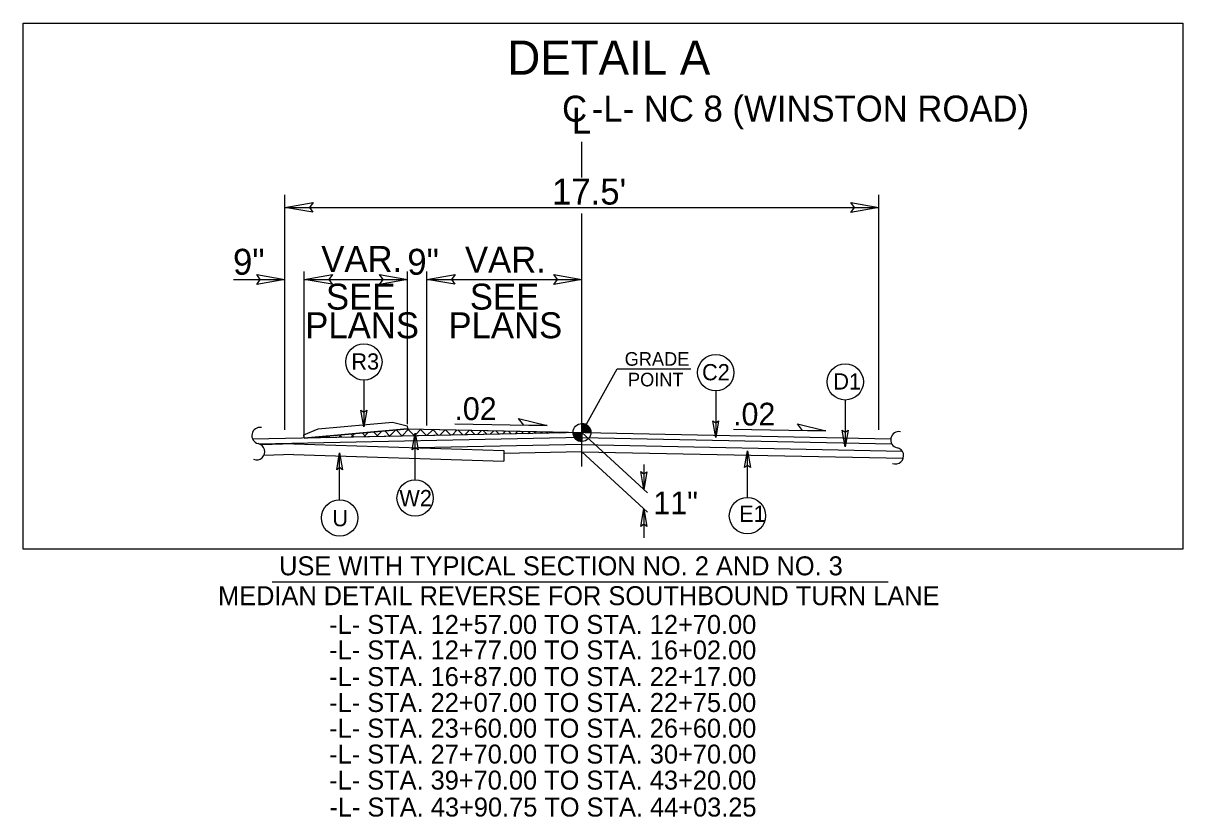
# Model space of a CAD drawing. Extents: x 957297 to 961629, y 830661 to 840840.
# Drawn here: x 960706.7 to 961104.7, y 838935.9 to 839208.2 of the extents above; entities that cross this region are included whole.
import ezdxf

# ---------------------------------------------------------------- set-up
doc = ezdxf.new("R2010")
doc.units = 0
for name, color, linetype in [('Old_Level_1', 7, 'Continuous'), ('Old_Level_11', 7, 'Continuous'), ('Old_Level_3', 7, 'Continuous'), ('Prop Dimension Text', 7, 'Continuous'), ('Typical ID Circle CELL', 7, 'Continuous'), ('Typical Terminator CELL', 7, 'Continuous'), ('Typical Text Grade Point CELL', 7, 'Continuous'), ('Typical Text ID Circle CELL', 7, 'Continuous')]:
    doc.layers.add(name, color=color, linetype=linetype)

msp = doc.modelspace()

# ---------------------------------------------------------------- linework, layer by layer
at = {"layer": 'Old_Level_1'}
for p, q in [((960898.52, 839155.33), (960898.52, 839167.52)), ((960796.56, 839068.71), (960796.56, 839149.38)), ((961000.47, 839068.71), (961000.47, 839149.38)), ((960796.56, 839145), (961000.47, 839145)), ((960898.52, 839056.06), (960898.52, 839142.96)), ((960778.93, 839120.3), (960796.56, 839120.3)), ((960803.21, 839065.85), (960803.21, 839123.05)), ((960803.21, 839120.3), (960838.67, 839120.3)), ((960838.67, 839070.68), (960838.67, 839123.05)), ((960845.32, 839070.15), (960845.32, 839123.05)), ((960845.32, 839120.3), (960898.52, 839120.3)), ((960898.52, 839067.78), (960910.57, 839089.56)), ((960838.61, 839068.99), (961004.51, 839065.63)), ((960854.93, 839070.79), (960886.53, 839070.15)), ((960898.52, 839067.78), (960898.52, 839070.84)), ((960950.58, 839068.93), (960982.18, 839068.3)), ((960898.52, 839067.78), (960785.49, 839065.49)), ((960898.52, 839066.05), (960787.89, 839063.81)), ((960895.45, 839067.78), (960898.52, 839067.78)), ((960901.58, 839067.78), (960898.52, 839067.78)), ((960898.52, 839064.73), (960898.52, 839067.78)), ((960898.52, 839067.78), (960898.52, 839064.73)), ((960898.52, 839067.78), (960921.02, 839047.06)), ((960898.52, 839066.05), (961004.85, 839063.9)), ((960930.2, 839065.45), (960930.24, 839065.4)), ((960898.52, 839063.62), (960842.44, 839062.49)), ((960871.72, 839061.57), (960871.72, 839057.89)), ((960898.52, 839061.13), (960871.72, 839060.59)), ((960898.52, 839063.62), (961008.41, 839061.4)), ((960898.52, 839061.13), (961008.79, 839058.9)), ((960898.52, 839061.13), (960921.02, 839040.41)), ((960919.76, 839056.73), (960919.76, 839048.22)), ((960919.75, 839041.59), (960919.75, 839031.63)), ((960792.18, 839016.56), (961003.59, 839016.56))]:
    msp.add_line(p, q, dxfattribs=at)
msp.add_lwpolyline([(960706.74, 839208.24), (961104.74, 839208.24), (961104.74, 839027.68), (960706.74, 839027.68)], close=True, dxfattribs=at)
for points in [[(960898.55, 839070.84), (960898.55, 839070.84), (960898.55, 839067.78)], [(960898.61, 839070.84), (960898.61, 839067.78)], [(960898.67, 839070.84), (960898.67, 839067.78)], [(960898.74, 839070.83), (960898.74, 839067.78)], [(960898.8, 839070.83), (960898.8, 839067.78)], [(960898.86, 839070.83), (960898.86, 839067.78)], [(960898.92, 839070.81), (960898.92, 839067.78)], [(960898.98, 839070.81), (960898.98, 839067.78)], [(960899.03, 839070.79), (960899.03, 839067.78)], [(960899.09, 839070.79), (960899.09, 839067.78)], [(960899.16, 839070.78), (960899.16, 839067.78)], [(960899.22, 839070.76), (960899.22, 839067.78)], [(960899.28, 839070.74), (960899.28, 839067.78)], [(960899.34, 839070.72), (960899.34, 839067.78)], [(960899.41, 839070.71), (960899.41, 839067.78)], [(960899.46, 839070.68), (960899.46, 839067.78)], [(960899.53, 839070.67), (960899.53, 839067.78)], [(960899.59, 839070.65), (960899.59, 839067.78)], [(960899.65, 839070.63), (960899.65, 839067.78)], [(960899.72, 839070.6), (960899.72, 839067.78)], [(960899.78, 839070.58), (960899.78, 839067.78)], [(960899.84, 839070.54), (960899.84, 839067.78)], [(960899.89, 839070.52), (960899.89, 839067.78)], [(960899.95, 839070.49), (960899.95, 839067.78)], [(960900.01, 839070.46), (960900.01, 839067.78)], [(960900.08, 839070.42), (960900.08, 839067.78)], [(960900.14, 839070.38), (960900.14, 839067.78)], [(960900.2, 839070.33), (960900.2, 839067.78)], [(960900.26, 839070.29), (960900.26, 839067.78)], [(960900.32, 839070.26), (960900.32, 839067.78)], [(960900.38, 839070.21), (960900.38, 839067.78)], [(960900.44, 839070.16), (960900.44, 839067.78)], [(960900.51, 839070.11), (960900.51, 839067.78)], [(960900.57, 839070.05), (960900.57, 839067.78)], [(960900.63, 839069.99), (960900.63, 839067.78)], [(960900.7, 839069.93), (960900.7, 839067.78)], [(960900.75, 839069.87), (960900.75, 839067.78)], [(960900.81, 839069.81), (960900.81, 839067.78)], [(960900.87, 839069.74), (960900.87, 839067.78)], [(960900.93, 839069.65), (960900.93, 839067.78)], [(960901, 839069.58), (960901, 839067.78)], [(960901.06, 839069.49), (960901.06, 839067.78)], [(960901.12, 839069.4), (960901.12, 839067.78)], [(960901.17, 839069.29), (960901.17, 839067.78)], [(960901.23, 839069.19), (960901.23, 839067.78)], [(960901.3, 839069.04), (960901.3, 839067.78)], [(960901.36, 839068.9), (960901.36, 839067.78)], [(960901.42, 839068.74), (960901.42, 839067.78)], [(960901.49, 839068.53), (960901.49, 839067.78)], [(960901.55, 839068.22), (960901.55, 839067.78)], [(960895.48, 839067.78), (960895.48, 839067.46)], [(960895.54, 839067.78), (960895.54, 839067.09)], [(960895.6, 839067.78), (960895.6, 839066.87)], [(960895.66, 839067.78), (960895.66, 839066.69)], [(960895.73, 839067.78), (960895.73, 839066.55)], [(960895.79, 839067.78), (960895.79, 839066.42)], [(960895.84, 839067.78), (960895.84, 839066.3)], [(960895.9, 839067.78), (960895.9, 839066.19)], [(960895.97, 839067.78), (960895.97, 839066.1)], [(960896.03, 839067.78), (960896.03, 839066.01)], [(960896.09, 839067.78), (960896.09, 839065.92)], [(960896.15, 839067.78), (960896.15, 839065.85)], [(960896.21, 839067.78), (960896.21, 839065.79)], [(960896.27, 839067.78), (960896.27, 839065.71)], [(960896.33, 839067.78), (960896.33, 839065.64)], [(960896.4, 839067.78), (960896.4, 839065.59)], [(960896.46, 839067.78), (960896.46, 839065.54)], [(960896.52, 839067.78), (960896.52, 839065.47)], [(960896.58, 839067.78), (960896.58, 839065.43)], [(960896.65, 839067.78), (960896.65, 839065.37)], [(960896.7, 839067.78), (960896.7, 839065.33)], [(960896.76, 839067.78), (960896.76, 839065.28)], [(960896.82, 839067.78), (960896.82, 839065.25)], [(960896.88, 839067.78), (960896.88, 839065.19)], [(960896.95, 839067.78), (960896.95, 839065.16)], [(960897.01, 839067.78), (960897.01, 839065.12)], [(960897.07, 839067.78), (960897.07, 839065.09)], [(960897.13, 839067.78), (960897.13, 839065.07)], [(960897.19, 839067.78), (960897.19, 839065.03)], [(960897.25, 839067.78), (960897.25, 839065)], [(960897.32, 839067.78), (960897.32, 839064.98)], [(960897.38, 839067.78), (960897.38, 839064.94)], [(960897.44, 839067.78), (960897.44, 839064.93)], [(960897.5, 839067.78), (960897.5, 839064.9)], [(960897.55, 839067.78), (960897.55, 839064.88)], [(960897.62, 839067.78), (960897.62, 839064.87)], [(960897.68, 839067.78), (960897.68, 839064.84)], [(960897.74, 839067.78), (960897.74, 839064.83)], [(960897.8, 839067.78), (960897.8, 839064.82)], [(960897.86, 839067.78), (960897.86, 839064.8)], [(960897.93, 839067.78), (960897.93, 839064.78)], [(960897.98, 839067.78), (960897.98, 839064.78)], [(960898.04, 839067.78), (960898.04, 839064.77)], [(960898.11, 839067.78), (960898.11, 839064.75)], [(960898.17, 839067.78), (960898.17, 839064.75)], [(960898.23, 839067.78), (960898.23, 839064.75)], [(960898.3, 839067.78), (960898.3, 839064.73)], [(960898.36, 839067.78), (960898.36, 839064.73)], [(960898.41, 839067.78), (960898.41, 839064.73)], [(960898.47, 839067.78), (960898.47, 839064.73), (960898.47, 839064.73)], [(960799.59, 839063.84), (960788.38, 839063.56)], [(960799.59, 839063.84), (960871.72, 839061.57)], [(960799.48, 839060.16), (960789.31, 839059.84)], [(960799.48, 839060.16), (960871.72, 839057.89)]]:
    msp.add_lwpolyline(points, dxfattribs=at)
msp.add_circle((960898.52, 839067.78), 3.06, dxfattribs=at)
for centre, radius, start, end in [((960788.03, 839066.7), 2.81, 79.4545, 256.8065), ((960898.52, 839067.78), 3.06, 359.9905, 89.9905), ((960898.52, 839067.78), 3.06, 179.9905, 269.9905), ((961007.3, 839065.27), 2.81, 79.4545, 256.8065), ((960786.85, 839061.2), 2.81, 248.3355, 78.8593), ((961006.12, 839059.77), 2.81, 248.3355, 78.8593)]:
    msp.add_arc(centre, radius, start, end, dxfattribs=at)
at = {"layer": 'Old_Level_11'}
for p, q in [((960878.52, 839070.31), (960876.79, 839072.57)), ((960876.79, 839072.57), (960886.53, 839070.15)), ((960886.53, 839070.15), (960878.52, 839070.31)), ((960974.18, 839068.46), (960972.45, 839070.71)), ((960972.45, 839070.71), (960982.18, 839068.3)), ((960982.18, 839068.3), (960974.18, 839068.46))]:
    msp.add_line(p, q, dxfattribs=at)
for points in [[(960806.18, 839143.35), (960796.56, 839145), (960806.23, 839146.71), (960805, 839145)], [(960990.85, 839146.66), (961000.47, 839145), (960990.8, 839143.29), (960992.03, 839145)], [(960786.95, 839121.95), (960796.56, 839120.3), (960786.89, 839118.59), (960788.12, 839120.3)], [(960812.83, 839118.64), (960803.21, 839120.3), (960812.88, 839122.01), (960811.65, 839120.3)], [(960829.06, 839121.95), (960838.67, 839120.3), (960829.01, 839118.59), (960830.24, 839120.3)], [(960854.94, 839118.64), (960845.32, 839120.3), (960854.99, 839122.01), (960853.76, 839120.3)], [(960888.9, 839121.95), (960898.52, 839120.3), (960888.85, 839118.59), (960890.08, 839120.3)]]:
    msp.add_lwpolyline(points, close=True, dxfattribs=at)
at = {"layer": 'Old_Level_3'}
for p, q in [((960803.11, 839066.95), (960807.96, 839069.06)), ((960838.6, 839068.99), (960803.21, 839065.85)), ((960807.96, 839069.06), (960833.44, 839071.32)), ((960827.99, 839066.35), (960829.85, 839068.21)), ((960830.85, 839068.3), (960832.7, 839066.44)), ((960832.32, 839066.44), (960834.51, 839068.62)), ((960833.44, 839071.32), (960838.58, 839070.1)), ((960834.74, 839068.64), (960836.86, 839066.53)), ((960836.65, 839066.52), (960839.11, 839068.98)), ((960838.58, 839070.1), (960838.6, 839068.99)), ((960838.64, 839068.99), (960841.02, 839066.61)), ((960841.38, 839067), (960843.26, 839068.89)), ((960842.97, 839068.9), (960845.18, 839066.7)), ((960845.31, 839066.7), (960847.42, 839068.81)), ((960847.3, 839068.81), (960849.33, 839066.78)), ((960849.65, 839066.79), (960851.58, 839068.72)), ((960851.63, 839068.72), (960853.49, 839066.87)), ((960853.98, 839066.87), (960855.74, 839068.64)), ((960855.96, 839068.64), (960857.65, 839066.95)), ((960858.31, 839066.96), (960859.9, 839068.56)), ((960860.29, 839068.55), (960861.81, 839067.03)), ((960862.64, 839067.05), (960864.06, 839068.47)), ((960864.63, 839068.46), (960865.97, 839067.12)), ((960866.97, 839067.14), (960868.22, 839068.39)), ((960868.96, 839068.37), (960870.13, 839067.2)), ((960871.3, 839067.23), (960872.37, 839068.3)), ((960873.29, 839068.28), (960874.28, 839067.29)), ((960875.63, 839067.31), (960876.53, 839068.22)), ((960803.21, 839065.85), (960803.11, 839066.95)), ((960803.57, 839065.88), (960803.59, 839065.86)), ((960806.34, 839065.91), (960806.58, 839066.15)), ((960807.46, 839066.23), (960807.75, 839065.94)), ((960810.67, 839066), (960811.23, 839066.56)), ((960811.36, 839066.57), (960811.91, 839066.02)), ((960815, 839066.09), (960815.89, 839066.97)), ((960815.26, 839066.92), (960816.07, 839066.11)), ((960819.15, 839067.26), (960820.22, 839066.19)), ((960819.33, 839066.17), (960820.54, 839067.38)), ((960823.05, 839067.61), (960824.38, 839066.28)), ((960823.66, 839066.26), (960825.2, 839067.8)), ((960826.95, 839067.95), (960828.54, 839066.36)), ((960840.98, 839066.61), (960841.13, 839066.76)), ((960877.62, 839068.2), (960878.44, 839067.37)), ((960879.96, 839067.4), (960880.69, 839068.14)), ((960881.95, 839068.11), (960882.6, 839067.45)), ((960884.29, 839067.49), (960884.85, 839068.05)), ((960886.28, 839068.02), (960886.76, 839067.54)), ((960888.62, 839067.58), (960889.01, 839067.97)), ((960890.61, 839067.93), (960890.92, 839067.62)), ((960892.95, 839067.66), (960893.17, 839067.88)), ((960894.94, 839067.85), (960895.08, 839067.71))]:
    msp.add_line(p, q, dxfattribs=at)
msp.add_lwpolyline([(960803.21, 839065.85), (960838.6, 839068.99), (960898.52, 839067.78)], close=True, dxfattribs=at)
at = {"layer": 'Typical ID Circle CELL'}
for p, q in [((960823.67, 839085.75), (960823.67, 839069.66)), ((960944.45, 839082.09), (960944.45, 839066)), ((960988.89, 839078.91), (960988.89, 839062.82)), ((960841.27, 839051.5), (960841.27, 839067.58)), ((960815.36, 839044.67), (960815.36, 839060.75)), ((960955.32, 839045.43), (960955.32, 839061.52))]:
    msp.add_line(p, q, dxfattribs=at)
for centre in [(960823.67, 839091.98), (960944.45, 839088.31), (960988.89, 839085.14), (960841.27, 839045.27), (960815.36, 839038.44), (960955.32, 839039.21)]:
    msp.add_circle(centre, 6.23, dxfattribs=at)
at = {"layer": 'Typical Terminator CELL'}
for points in [[(960824.66, 839075.43), (960823.67, 839069.66), (960822.64, 839075.46), (960823.67, 839074.72)], [(960945.44, 839071.77), (960944.45, 839066), (960943.42, 839071.8), (960944.45, 839071.06)], [(960989.88, 839068.59), (960988.89, 839062.82), (960987.87, 839068.62), (960988.89, 839067.88)], [(960840.28, 839061.82), (960841.27, 839067.58), (960842.3, 839061.79), (960841.27, 839062.52)], [(960814.37, 839054.99), (960815.36, 839060.75), (960816.39, 839054.96), (960815.36, 839055.7)], [(960954.33, 839055.76), (960955.32, 839061.52), (960956.35, 839055.73), (960955.32, 839056.46)], [(960920.81, 839054.29), (960919.76, 839048.22), (960918.68, 839054.33), (960919.76, 839053.55)], [(960918.7, 839035.52), (960919.75, 839041.59), (960920.82, 839035.49), (960919.75, 839036.27)]]:
    msp.add_lwpolyline(points, close=True, dxfattribs=at)
at = {"layer": 'Typical Text Grade Point CELL'}
msp.add_line((960910.57, 839089.56), (960935.9, 839089.56), dxfattribs=at)

# ---------------------------------------------------------------- texts
at = {"layer": 'Old_Level_1'}
for s, height, p in [('DETAIL A', 11.716, (960872.9, 839190.57)), ('USE WITH TYPICAL SECTION NO. 2 AND NO. 3', 6.5088, (960794.59, 839018.75)), ('MEDIAN DETAIL REVERSE FOR SOUTHBOUND TURN LANE', 6.5088, (960773.63, 839008.5)), ('-L- STA. 12+57.00 TO STA. 12+70.00', 6.5088, (960811.76, 838998.64)), ('-L- STA. 12+77.00 TO STA. 16+02.00', 6.5088, (960811.76, 838989.89)), ('-L- STA. 16+87.00 TO STA. 22+17.00', 6.5088, (960811.76, 838980.73)), ('-L- STA. 22+07.00 TO STA. 22+75.00', 6.5088, (960811.76, 838971.85)), ('-L- STA. 23+60.00 TO STA. 26+60.00', 6.5088, (960811.76, 838963.03)), ('-L- STA. 27+70.00 TO STA. 30+70.00', 6.5088, (960811.76, 838954.14)), ('-L- STA. 39+70.00 TO STA. 43+20.00', 6.5088, (960811.76, 838945.21)), ('-L- STA. 43+90.75 TO STA. 44+03.25', 6.5088, (960811.84, 838935.96))]:
    msp.add_text(s, height=height, dxfattribs=at).set_placement(p)
at = {"layer": 'Old_Level_11'}
for s, p in [('GRADE', (960913.17, 839090.68)), ('POINT', (960914.31, 839083.6))]:
    msp.add_text(s, height=4.671, dxfattribs=at).set_placement(p)
at = {"layer": 'Old_Level_3'}
for s, p in [("17.5'", (960888.27, 839145.99)), ('9"', (960778.76, 839121.91)), ('VAR.', (960809.05, 839122.87)), ('9"', (960838.59, 839121.91)), ('VAR.', (960858.37, 839122.63)), ('SEE', (960810.66, 839109.95)), ('SEE', (960860.04, 839109.95)), ('PLANS', (960803.55, 839100.11)), ('PLANS', (960852.71, 839100.11))]:
    msp.add_text(s, height=8.9, rotation=0, dxfattribs=at).set_placement(p)
at = {"layer": 'Prop Dimension Text'}
for s, height, rotation, p in [('-L- NC 8 (WINSTON ROAD)', 8.9003, 0, (960901.9, 839174.5)), ('C', 8.9, 0, (960891.69, 839174.46)), ('L', 8.9, 0, (960895.09, 839170.37)), ('.02', 7.801, 360, (960854.74, 839072.03)), ('.02', 7.801, 360, (960950.39, 839070.17)), ('11"', 7.801, 0, (960923.02, 839039.7))]:
    msp.add_text(s, height=height, rotation=rotation, dxfattribs=at).set_placement(p)
at = {"layer": 'Typical Text ID Circle CELL'}
for s, height, p in [('R3', 5.572, (960819.38, 839089.35)), ('C2', 5.572, (960939.74, 839085.68)), ('D1', 5.572, (960984.8, 839082.51)), ('W2', 5.572, (960835.84, 839042.47)), ('U', 5.57, (960812.85, 839035.58)), ('E1', 5.572, (960952.44, 839037.08))]:
    msp.add_text(s, height=height, dxfattribs=at).set_placement(p)

doc.saveas('drawing.dxf')
